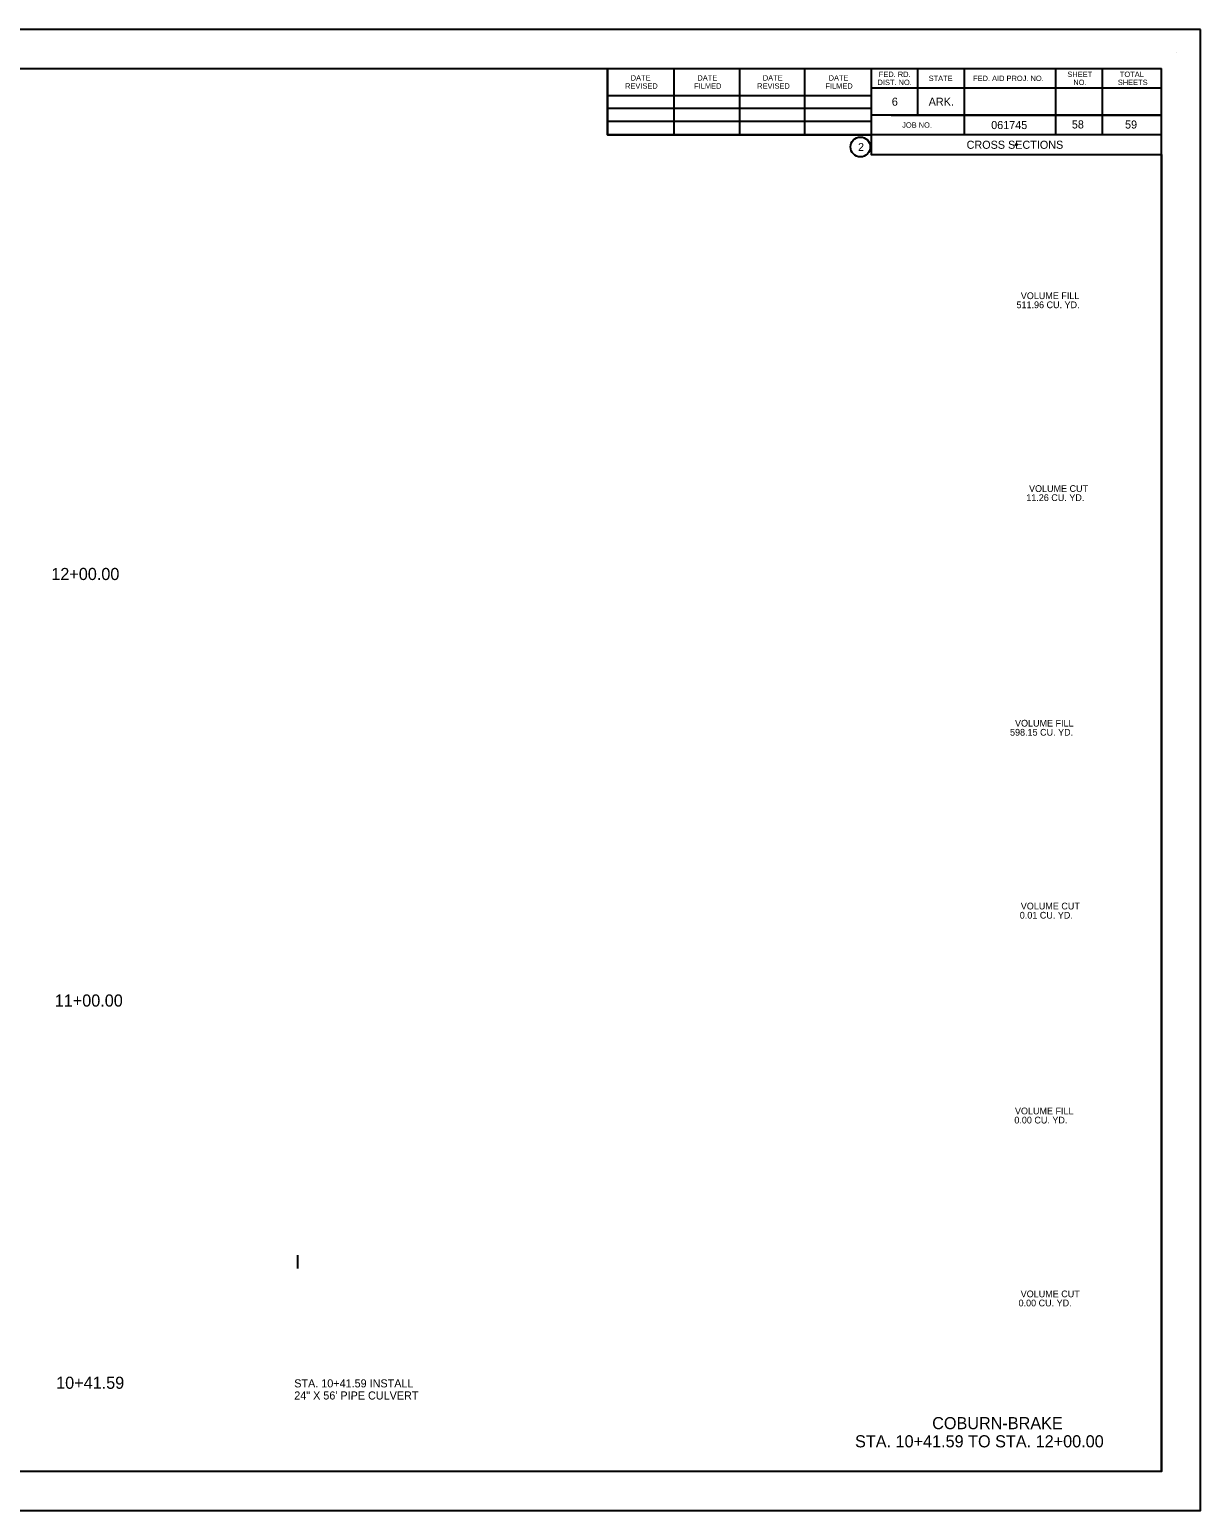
# Model space of a CAD drawing. Extents: x 1284907 to 1285667, y 403630 to 403851.
# Drawn here: x 1285073.5 to 1285247.4, y 403631.1 to 403851.1 of the extents above; entities that cross this region are included whole.
import ezdxf

# ---------------------------------------------------------------- set-up
doc = ezdxf.new("R2010")
doc.units = 0
for name, color, linetype in [('1', 7, 'Continuous'), ('Default', 7, 'Continuous'), ('NO PLOT CELL', 7, 'Continuous'), ('R_Draft', 7, 'Continuous'), ('R_Grid_Sta', 7, 'Continuous')]:
    doc.layers.add(name, color=color, linetype=linetype)

msp = doc.modelspace()

# ---------------------------------------------------------------- linework, layer by layer
at = {"layer": '1'}
for p, q in [((1285243.82, 403847.63), (1285243.82, 403847.63)), ((1284922.56, 403845.32), (1285241.63, 403845.32)), ((1285159.37, 403835.44), (1285159.37, 403845.32)), ((1285198.53, 403845.32), (1285198.53, 403832.52)), ((1285205.37, 403845.32), (1285205.37, 403838.38)), ((1285212.31, 403845.32), (1285212.31, 403835.44)), ((1285225.89, 403845.32), (1285225.89, 403835.44)), ((1285232.83, 403845.32), (1285232.83, 403835.44)), ((1285241.63, 403636.85), (1285241.63, 403845.32)), ((1285169.23, 403835.44), (1285169.23, 403845.12)), ((1285178.99, 403835.44), (1285178.99, 403845.12)), ((1285188.67, 403835.44), (1285188.67, 403845.12)), ((1285159.37, 403841.3), (1285198.53, 403841.3)), ((1285241.63, 403842.38), (1285198.53, 403842.38)), ((1285241.63, 403842.4), (1285241.63, 403842.4)), ((1285159.37, 403839.44), (1285198.53, 403839.44)), ((1285159.37, 403835.44), (1285159.37, 403837.5)), ((1285159.37, 403837.5), (1285198.53, 403837.5)), ((1285241.63, 403838.38), (1285198.53, 403838.38)), ((1285201.49, 403838.38), (1285241.63, 403838.38)), ((1285241.63, 403835.44), (1285159.37, 403835.44)), ((1285198.53, 403832.52), (1285241.63, 403832.52)), ((1285241.63, 403636.85), (1284922.56, 403636.85))]:
    msp.add_line(p, q, dxfattribs=at)
for points in [[(1285247.4, 403851.09), (1284907.4, 403851.09), (1284907.4, 403631.09), (1285247.4, 403631.09)], [(1284922.56, 403636.85), (1284922.56, 403845.32), (1285159.37, 403845.32), (1285159.37, 403835.44), (1285198.53, 403835.44), (1285198.53, 403832.52), (1285241.63, 403832.52), (1285241.63, 403636.85)]]:
    msp.add_lwpolyline(points, close=True, dxfattribs=at)
msp.add_circle((1285196.91, 403833.65), 1.47, dxfattribs=at)
at = {"layer": 'Default'}
msp.add_line((1285113.32, 403669.02), (1285113.32, 403667.02), dxfattribs=at)
at = {"layer": 'NO PLOT CELL'}
msp.add_circle((1285220.08, 403833.98), 0.1, dxfattribs=at)

# ---------------------------------------------------------------- texts
at = {"layer": '1'}
for s, height, p in [('REVISED', 0.8, (1285161.96, 403842.31)), ('DATE', 0.8, (1285162.8, 403843.51)), ('FILMED', 0.8, (1285172.22, 403842.31)), ('DATE', 0.8, (1285172.7, 403843.51)), ('REVISED', 0.8, (1285181.58, 403842.31)), ('DATE', 0.8, (1285182.42, 403843.51)), ('FILMED', 0.8, (1285191.71, 403842.31)), ('DATE', 0.8, (1285192.19, 403843.51)), ('DIST. NO.', 0.8, (1285199.45, 403842.85)), ('FED. RD.', 0.8, (1285199.64, 403844.05)), ('STATE', 0.8, (1285207.04, 403843.45)), ('FED. AID PROJ. NO.', 0.8, (1285213.64, 403843.45)), ('SHEET', 0.8, (1285227.64, 403844.05)), ('NO.', 0.8, (1285228.53, 403842.85)), ('SHEETS', 0.8, (1285235.14, 403842.85)), ('TOTAL', 0.8, (1285235.44, 403844.05)), ('6', 1.2, (1285201.57, 403839.78)), ('ARK.', 1.2, (1285207.05, 403839.78)), ('JOB NO.', 0.8, (1285203.11, 403836.51)), ('061745', 1.2, (1285216.33, 403836.31)), ('58', 1.2, (1285228.31, 403836.4)), ('59', 1.2, (1285236.21, 403836.39)), ('2', 1.17, (1285196.57, 403833.07)), ('CROSS SECTIONS', 1.2, (1285212.68, 403833.38))]:
    msp.add_text(s, height=height, dxfattribs=at).set_placement(p)
at = {"layer": 'Default'}
for s, p in [('511.96 CU. YD.', (1285220.09, 403809.7)), ('VOLUME FILL', (1285220.73, 403811.05)), ('11.26 CU. YD.', (1285221.54, 403781.05)), ('VOLUME CUT', (1285221.95, 403782.4)), ('VOLUME FILL', (1285219.87, 403747.54)), ('598.15 CU. YD.', (1285219.13, 403746.19)), ('0.01 CU. YD.', (1285220.58, 403719.01)), ('VOLUME CUT', (1285220.73, 403720.37)), ('0.00 CU. YD.', (1285219.77, 403688.57)), ('VOLUME FILL', (1285219.86, 403689.93)), ('VOLUME CUT', (1285220.71, 403662.75)), ('0.00 CU. YD.', (1285220.4, 403661.4))]:
    msp.add_text(s, height=1, dxfattribs=at).set_placement(p)
at = {"layer": 'R_Draft'}
for s, p in [('STA. 10+41.59 INSTALL ', (1285112.83, 403649.36)), ('24" X 56\' PIPE CULVERT ', (1285112.83, 403647.56))]:
    msp.add_text(s, height=1.2, rotation=359.9935, dxfattribs=at).set_placement(p)
at = {"layer": 'R_Grid_Sta'}
for s, p in [('12+00.00', (1285076.75, 403769.31)), ('11+00.00', (1285077.26, 403705.94)), ('10+41.59', (1285077.47, 403649.15)), ('COBURN-BRAKE', (1285207.57, 403643.15)), ('STA. 10+41.59 TO STA. 12+00.00', (1285196.11, 403640.45))]:
    msp.add_text(s, height=1.8, dxfattribs=at).set_placement(p)

doc.saveas('drawing.dxf')
